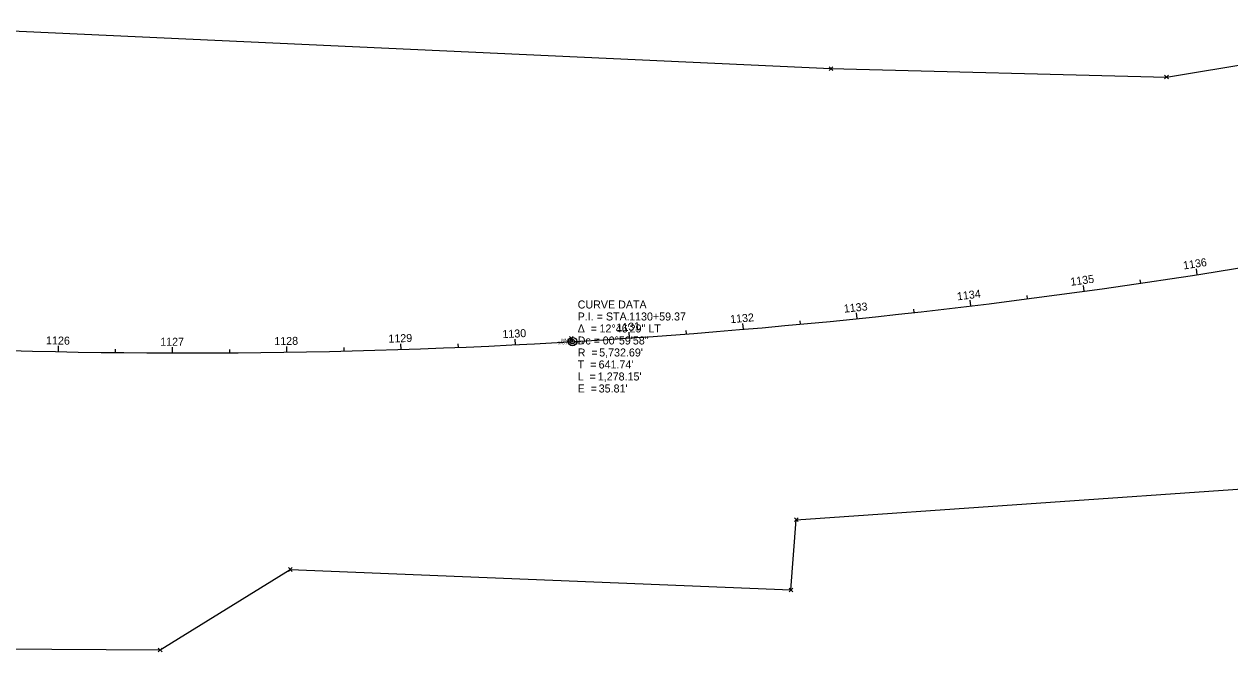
# Model space of a CAD drawing. Extents: x 2082101 to 2090447, y 708207 to 709766.
# Drawn here: x 2084181 to 2085236, y 708207 to 708756 of the extents above; entities that cross this region are included whole.
import ezdxf

# ---------------------------------------------------------------- set-up
doc = ezdxf.new("R2010")
doc.units = 0
for name, color, linetype in [('DR_X_Cells', 7, 'Continuous'), ('DR_X_Ditch', 7, 'Continuous'), ('GK_Drainage_Nodes', 7, 'Continuous'), ('SV_X_Break_Lines', 7, 'Continuous'), ('SV_X_Mon_Cells_Found', 7, 'Continuous'), ('SV_X_Shot_Marker', 7, 'Continuous'), ('SV_X_Text_Comment', 7, 'Continuous'), ('SV_X_Text_Elevation', 7, 'Continuous'), ('SV_X_Text_Name', 7, 'Continuous'), ('SV_X_Toe_of_Slope', 7, 'Continuous')]:
    doc.layers.add(name, color=color, linetype=linetype)

msp = doc.modelspace()

# ---------------------------------------------------------------- linework, layer by layer
at = {"layer": 'DR_X_Ditch'}
for p, q in [((2084042.9, 708756.1), (2084886.6, 708717.1)), ((2084042.9, 708756.1), (2084886.6, 708717.1)), ((2085180.1, 708709.7), (2085275.9, 708725.5)), ((2085180.1, 708709.7), (2085275.9, 708725.5)), ((2084886.6, 708717.1), (2085180.1, 708709.7)), ((2084886.6, 708717.1), (2085180.1, 708709.7)), ((2084856.3, 708322.4), (2085288.2, 708352.3)), ((2084851.6, 708260.9), (2084856.3, 708322.4)), ((2084299.6, 708208.4), (2084413.5, 708278.8)), ((2084413.5, 708278.8), (2084851.6, 708260.9)), ((2083922, 708211.1), (2084299.6, 708208.4))]:
    msp.add_line(p, q, dxfattribs=at)
at = {"layer": 'GK_Drainage_Nodes'}
for p, q in [((2085207.1, 708536.8), (2085206.3, 708541.8)), ((2085157.7, 708529.3), (2085157.2, 708532.3)), ((2085108.2, 708522.3), (2085107.5, 708527.2)), ((2085009, 708509.5), (2085008.4, 708514.4)), ((2085058.6, 708515.6), (2085058.2, 708518.6)), ((2084909.6, 708498.4), (2084909.1, 708503.3)), ((2084959.3, 708503.7), (2084959, 708506.7)), ((2084810.1, 708489), (2084809.6, 708494)), ((2084859.9, 708493.5), (2084859.6, 708496.5)), ((2084610.5, 708475.5), (2084610.3, 708480.5)), ((2084660.4, 708478.2), (2084660.3, 708481.2)), ((2084710.3, 708481.4), (2084710, 708486.4)), ((2084760.2, 708485), (2084760, 708488)), ((2084210.6, 708469.4), (2084210.7, 708474.4)), ((2084260.6, 708468.7), (2084260.7, 708471.7)), ((2084310.6, 708468.3), (2084310.6, 708473.3)), ((2084360.6, 708468.4), (2084360.6, 708471.4)), ((2084410.6, 708469), (2084410.6, 708474)), ((2084460.6, 708470), (2084460.6, 708473)), ((2084510.6, 708471.4), (2084510.4, 708476.4)), ((2084560.6, 708473.2), (2084560.4, 708476.2))]:
    msp.add_line(p, q, dxfattribs=at)
at = {"layer": 'SV_X_Break_Lines'}
for p, q in [((2084884.9, 708715.4), (2084888.2, 708718.7)), ((2084884.9, 708718.7), (2084888.2, 708715.4)), ((2085178.5, 708708.1), (2085181.8, 708711.4)), ((2085178.5, 708711.4), (2085181.8, 708708.1)), ((2084854.6, 708320.7), (2084857.9, 708324.1)), ((2084854.6, 708324.1), (2084857.9, 708320.7)), ((2084411.9, 708277.1), (2084415.2, 708280.5)), ((2084411.9, 708280.5), (2084415.2, 708277.1)), ((2084850, 708259.2), (2084853.3, 708262.5)), ((2084850, 708262.5), (2084853.3, 708259.2)), ((2084297.9, 708206.7), (2084301.3, 708210)), ((2084297.9, 708210), (2084301.3, 708206.7))]:
    msp.add_line(p, q, dxfattribs=at)
at = {"layer": 'SV_X_Shot_Marker'}
msp.add_arc((2084323.5, 714201), 5732.7, 267.0489, 279.82352, dxfattribs=at)
at = {"layer": 'SV_X_Text_Name'}
for p, q in [((2084657.7, 708479.3), (2084661, 708482.6)), ((2084657.7, 708482.6), (2084661, 708479.3))]:
    msp.add_line(p, q, dxfattribs=at)
at = {"layer": 'SV_X_Toe_of_Slope'}
for radius in [3.75, 2]:
    msp.add_circle((2084660.4, 708478.2), radius, dxfattribs=at)

# ---------------------------------------------------------------- texts
at = {"layer": 'DR_X_Cells'}
for s, p in [('CURVE DATA', (2084665, 708507.2)), ('P.I. = STA. ', (2084665, 708496.7)), ('1130+59.37', (2084710, 708496.7)), ('Δ  = ', (2084665, 708486.2)), ('12°46\'29" LT', (2084684.1, 708486.2)), ('Dc = ', (2084665, 708475.7)), ('00°59\'58"', (2084686.9, 708475.7)), ('R  = ', (2084665, 708465.2)), ("5,732.69'", (2084683.8, 708465.2)), ('T  = ', (2084665, 708454.7)), ("641.74'", (2084683.3, 708454.7)), ('L  = ', (2084665, 708444.2)), ("1,278.15'", (2084682.6, 708444.2)), ('E  = ', (2084665, 708433.7)), ("35.81'", (2084683.4, 708433.7))]:
    msp.add_text(s, height=7, dxfattribs=at).set_placement(p)
at = {"layer": 'GK_Drainage_Nodes'}
for s, rotation, p in [('1136', 8.8661, (2085195.3, 708541.3)), ('1135', 7.8667, (2085096.6, 708527)), ('1134', 6.8672, (2084997.3, 708514.3)), ('1133', 5.8678, (2084898.2, 708503.5)), ('1132', 4.8683, (2084798.7, 708494.3)), ('1130', 2.8694, (2084599.3, 708481.2)), ('1131', 3.8688, (2084699.1, 708486.9)), ('1126', 358.8716, (2084199.8, 708475.9)), ('1127', 359.871, (2084299.7, 708474.6)), ('1128', 0.8705, (2084399.6, 708475.1)), ('1129', 1.8699, (2084499.5, 708477.3))]:
    msp.add_text(s, height=7, rotation=rotation, dxfattribs=at).set_placement(p)
at = {"layer": 'SV_X_Mon_Cells_Found'}
msp.add_text('CMON', height=2.5, dxfattribs=at).set_placement((2084660.4, 708475.7))
at = {"layer": 'SV_X_Text_Comment'}
msp.add_text('926.162', height=2.5, dxfattribs=at).set_placement((2084647.7, 708475.7))
at = {"layer": 'SV_X_Text_Elevation'}
msp.add_text('MN15', height=2.5, dxfattribs=at).set_placement((2084650.8, 708478.2))

doc.saveas('drawing.dxf')
